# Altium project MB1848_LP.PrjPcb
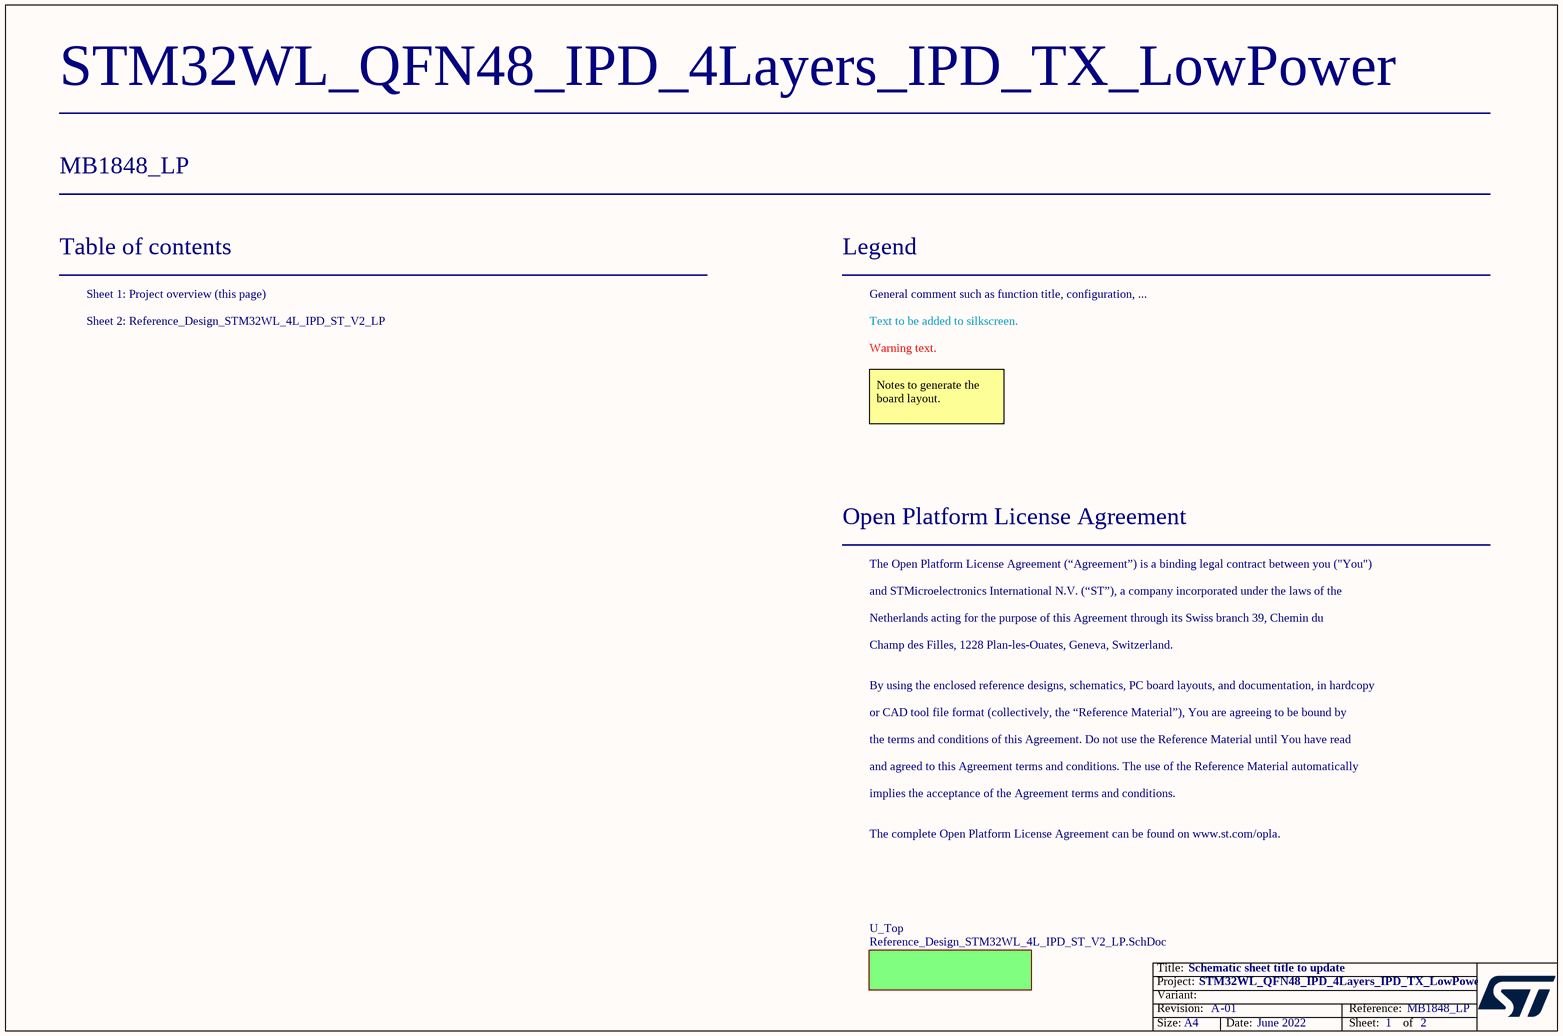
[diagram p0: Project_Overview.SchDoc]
Board_Assembly_Revision: 01; Board_Document_Date: June 2022; Board_Name: STM32WL_QFN48_IPD_4Layers_IPD_TX_LowPower; Board_PCB_Revision: A; Board_Reference: MB1848_LP
2 sheets, 71 parts. Net scope: flat (ports and power ports of the same name join across sheets).
Board file: MB1848_LP.PcbDoc
Sheets:
  Project_Overview.SchDoc
    U_Top = Reference_Design_STM32WL_4L_IPD_ST_V2_LP.SchDoc

## Sheet Project_Overview.SchDoc: Schematic sheet title to update
size A4; Date: Not used; ApprovedBy: Not used; CheckedBy: Not used; Author: Not used; CompanyName: STMicroelectronics; DrawnBy: Not used; Engineer: Not used; Organization: Not used; Address1: Not used; Address2: Not used; Address3: Not used; Address4: Not used; DocumentNumber: Not used; Revision: Not used; SheetNumber: 1; SheetTotal: 2

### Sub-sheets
U_Top = Reference_Design_STM32WL_4L_IPD_ST_V2_LP.SchDoc: no entries

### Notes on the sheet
- Table of contents
- Sheet 1: Project overview (this page)
- Legend
- General comment such as function title, configuration, ...
- Sheet 2: Reference_Design_STM32WL_4L_IPD_ST_V2_LP
- Text to be added to silkscreen.
- Warning text.
- Notes to generate the board layout.
- Open Platform License Agreement
- The Open Platform License Agreement (“Agreement”) is a binding legal contract between you ("You")
- and STMicroelectronics International N.V. (“ST”), a company incorporated under the laws of the
- Netherlands acting for the purpose of this Agreement through its Swiss branch 39, Chemin du
- Champ des Filles, 1228 Plan-les-Ouates, Geneva, Switzerland.
- By using the enclosed reference designs, schematics, PC board layouts, and documentation, in hardcopy
- or CAD tool file format (collectively, the “Reference Material”), You are agreeing to be bound by
- the terms and conditions of this Agreement. Do not use the Reference Material until You have read
- and agreed to this Agreement terms and conditions. The use of the Reference Material automatically
- implies the acceptance of the Agreement terms and conditions.
- The complete Open Platform License Agreement can be found on www.st.com/opla.

## Sheet Reference_Design_STM32WL_4L_IPD_ST_V2_LP.SchDoc: Schematic sheet title to update
size A3; Date: Not used; ApprovedBy: Not used; CheckedBy: Not used; Author: Not used; CompanyName: STMicroelectronics; DrawnBy: Not used; Engineer: Not used; Organization: Not used; Address1: Not used; Address2: Not used; Address3: Not used; Address4: Not used; DocumentNumber: Not used; Revision: Not used; SheetNumber: 2; SheetTotal: 2
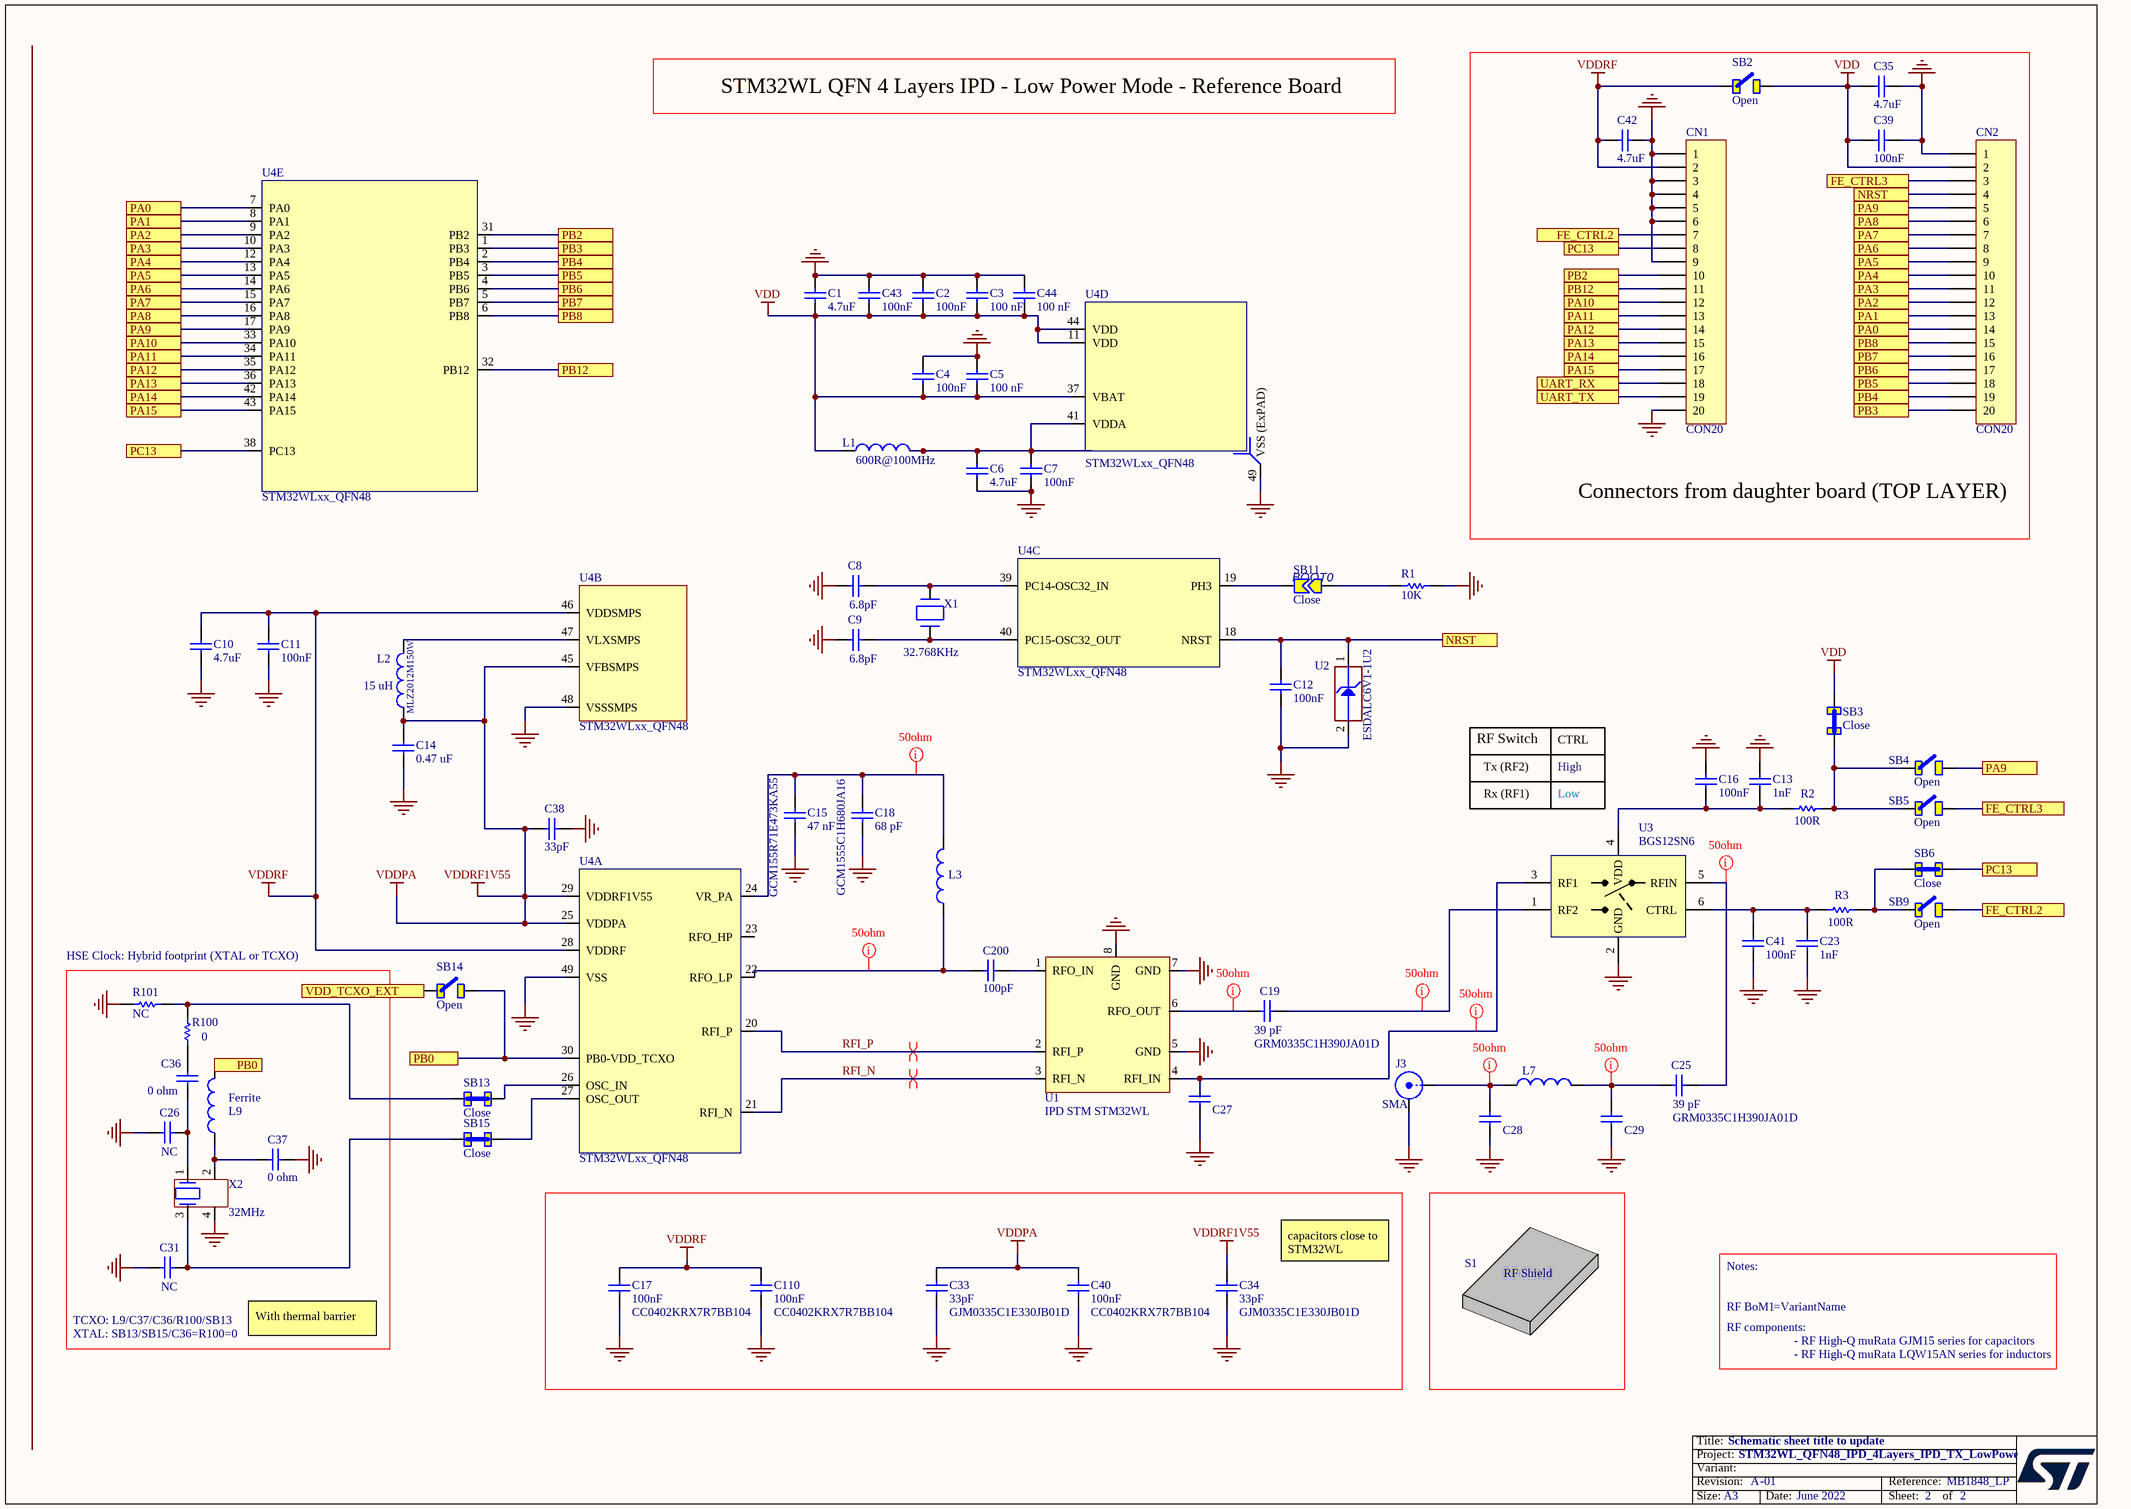
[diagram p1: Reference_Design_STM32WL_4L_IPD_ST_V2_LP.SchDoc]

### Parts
C1  value 4.7uF  [CAPC1608X09N]
C2  value 100nF  [CAPC1005X06N]
C3  value 100 nF  [0201]
C4  value 100nF  [CAPC1005X06N]
C5  value 100 nF  [0201]
C6  value 4.7uF  [CAPC1608X09N]
C7  value 100nF  [CAPC1005X06N]
C8  value 6.8pF  [0402]  (hidden comment: Capacitor)
C9  value 6.8pF  [0402]  (hidden comment: Capacitor)
C10  value 4.7uF  [CAPC1608X09N]
C11  value 100nF  [CAPC1005X06N]
C12  value 100nF  [0402]
C13  value 1nF  [0201]  (hidden comment: MCD-00198)
C14  value 0.47 uF  [CAPC1608X09N]
C15  value 47 nF  Manufacturer_Part_Number: GCM155R71E473KA55  [0402]
C16  value 100nF  [0201]  (hidden comment: MCD-00102)
C17  value 100nF  Manufacturer_Part_Number: CC0402KRX7R7BB104  [CAPC1005X06N]
C18  value 68 pF  Manufacturer_Part_Number: GCM1555C1H680JA16  [0402]
C19  value 39 pF  Manufacturer_Part_Number: GRM0335C1H390JA01D  [rlc_201_smd]  (hidden comment: RFCapacitor_201)
C23  value 1nF  [0201]  (hidden comment: MCD-00198)
C25  value 39 pF  Manufacturer_Part_Number: GRM0335C1H390JA01D  [rlc_201_smd]  (hidden comment: RFCapacitor_201)
C26  value NC  [0402]  (hidden comment: Capacitor)
C27  NC  [0201]  (value not drawn)
C28  RFCapacitor_201  [rlc_201_smd]  (value not drawn)
C29  RFCapacitor_201  [rlc_201_smd]  (value not drawn)
C31  value NC  [0402]  (hidden comment: Capacitor)
C33  value 33pF  Manufacturer_Part_Number: GJM0335C1E330JB01D  [0201]
C34  value 33pF  Manufacturer_Part_Number: GJM0335C1E330JB01D  [0201]
C35  value 4.7uF  [CAPC1608X09N]
C36  value 0 ohm  [0402]
C37  value 0 ohm  [0402]
C38  value 33pF  [0201]
C39  value 100nF  [CAPC1005X06N]
C40  value 100nF  Manufacturer_Part_Number: CC0402KRX7R7BB104  [CAPC1005X06N]
C41  value 100nF  [0201]  (hidden comment: MCD-00102)
C42  value 4.7uF  [CAPC1608X09N]
C43  value 100nF  [CAPC1005X06N]
C44  value 100 nF  [0201]
C110  value 100nF  Manufacturer_Part_Number: CC0402KRX7R7BB104  [CAPC1005X06N]
C200  value 100pF  [0201]  (hidden comment: MCD-00198)
CN1  CON20  [CO_SAMTEC_TSW-120-07-x-S]
CN2  CON20  [CO_SAMTEC_TSW-120-07-x-S]
J3  SMA  [SMA_AMPHENOL_50ohms_Edge_PCB]
L1  value 600R@100MHz  [INDC1608X95N]
L2  value 15 uH  Manufacturer_Part_Number: MLZ2012M150W  [INDC2012X13N]
L3  MCD-01330  [IND_MURATA_LQW15A]  (value not drawn)
L7  Ferrite  [rlc_201_smd]  (value not drawn)
L9  Ferrite  [IND_MURATA_LQW15A]
R1  value 10K  [RESC1608X05N]
R2  value 100R  [0201]  (hidden comment: MCD-00119)
R3  value 100R  [0201]  (hidden comment: MCD-00119)
R100  value 0  [R0402]  (hidden comment: Resistor)
R101  value NC  [R0402]  (hidden comment: Resistor)
RF_BoM1  RF-BOM  (value not drawn)  (mechanical)
S1  RF-Shield  (value not drawn)  (mechanical)
SB2  Open  [SB_0402]
SB3  Close  [0201]
SB4  Open  [0201]
SB5  Open  [0201]
SB6  Close  [0201]
SB9  Open  [0201]
SB11  Close  [GC_0402]
SB13  Close  [SB_0402]
SB14  Open  [SB_0402]
SB15  Close  [SB_0402]
U1  IPD STM STM32WL  [IPD STM]
U2  Manufacturer_Part_Number: ESDALC6V1-1U2  [DIOM0603X03N]
U3  BGS12SN6  [TSNP-6-2]
U4  STM32WLxx_QFN48  [STM32WLxx_QFN48]  (parts A,B,C,D,E of 5)
X1  value 32.768KHz  [OSC_NDK_NX2012SA]  (hidden comment: XTAL_2_PINS)
X2  value 32MHz  [OSC_NDK_NX2016SA]

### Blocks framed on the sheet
Connectors from daughter board (TOP LAYER): C35 C39 C42 CN1 CN2 SB2

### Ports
FE_CTRL2, FE_CTRL3, NRST, PA0, PA1, PA2, PA3, PA4, PA5, PA6, PA7, PA8, PA9, PA10, PA11, PA12, PA13, PA14, PA15, PB0, PB2, PB3, PB4, PB5, PB6, PB7, PB8, PB12, PC13, UART_RX, UART_TX, VDD_TCXO_EXT

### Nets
GND: C1.1 C2.1 C3.1 C4.1 C5.1 C6.2 C7.2 C8.2 C9.2 C10.2 C11.2 C12.2 C13.1 C14.2 C15.2 C16.1 C17.2 C18.1 C23.1 C26.2 C27.1 C28.1 C29.1 C31.2 C33.1 C34.1 C35.1 C37.1 C38.2 C39.2 C40.2 C41.2 C42.2 C43.1 C44.1 C110.2 CN1.1 CN1.3 CN1.4 CN1.5 CN1.6 CN1.9 CN1.20 CN2.1 J3.2(GND) R1.1 R101.2 U1.5(GND) U1.7(GND) U1.8(GND) U2.2(GND) U3.2(GND) U4.48(VSSSMPS) U4.49(VSS_(ExPAD)) X2.4
VDD: C1.2 C2.2 C3.2 C4.2 C5.2 C35.2 C39.1 C43.2 C44.2 CN2.2 L1.1 SB2.1 SB3.1 U4.11(VDD) U4.37(VBAT) U4.44(VDD)
VDDPA: C14.1 C33.2 C34.2 C38.1 C40.1 L2.1 U4.25(VDDPA) U4.29(VDDRF1V55) U4.45(VFBSMPS)  [also labelled VDDRF1V55]
VDDRF: C10.1 C11.1 C17.1 C42.1 C110.1 CN1.2 SB2.2 U4.28(VDDRF) U4.46(VDDSMPS)
RFI_N: U1.3(RFI_N) U4.21(RFI_N)
RFI_P: U1.2(RFI_P) U4.20(RFI_P)
NetC6_1: C6.1 C7.1 L1.2 U4.41(VDDA)
NetC8_1: C8.1 U4.39(PC14-OSC32_IN) X1.2(X2)
NetC9_1: C9.1 U4.40(PC15-OSC32_OUT) X1.1(X1)
NetC12_1: C12.1 CN2.4 U2.1(IO1) U4.18(NRST) ; port NRST
NetC13_2: C13.2 C16.2 R2.1 U3.4(VDD)
NetC15_1: C15.1 C18.2 L3.1 U4.24(VR_PA)
NetC19_1: C19.1 U3.1(RF2)
NetC19_2: C19.2 U1.6(RFO_OUT)
NetC23_2: C23.2 C41.1 R3.1 U3.6(CTRL)
NetC25_1: C25.1 U3.5(RFIN)
NetC25_2: C25.2 C29.2 L7.1
NetC26_1: C26.1 C36.2 X2.1
NetC27_2: C27.2 U1.4(RFI_IN) U3.3(RF1)
NetC28_2: C28.2 J3.1(Signal) L7.2
NetC31_1: C31.1 SB15.2 X2.3
NetC36_1: C36.1 R100.2
NetC37_2: C37.2 L9.1 X2.2
NetC200_1: C200.1 U1.1(RFO_IN)
NetC200_2: C200.2 L3.2 U4.22(RFO_LP)
NetCN1_7: CN1.7 SB9.1 ; port FE_CTRL2
NetCN1_8: CN1.8 SB6.1 U4.38(PC13) ; port PC13
NetCN1_10: CN1.10 U4.31(PB2) ; port PB2
NetCN1_11: CN1.11 U4.32(PB12) ; port PB12
NetCN1_12: CN1.12 U4.33(PA10) ; port PA10
NetCN1_13: CN1.13 U4.34(PA11) ; port PA11
NetCN1_14: CN1.14 U4.35(PA12) ; port PA12
NetCN1_15: CN1.15 U4.36(PA13) ; port PA13
NetCN1_16: CN1.16 U4.42(PA14) ; port PA14
NetCN1_17: CN1.17 U4.43(PA15) ; port PA15
NetCN1_18: CN1.18 ; port UART_RX
NetCN1_19: CN1.19 ; port UART_TX
NetCN2_3: CN2.3 SB5.1 ; port FE_CTRL3
NetCN2_5: CN2.5 SB4.1 U4.17(PA9) ; port PA9
NetCN2_6: CN2.6 U4.16(PA8) ; port PA8
NetCN2_7: CN2.7 U4.15(PA7) ; port PA7
NetCN2_8: CN2.8 U4.14(PA6) ; port PA6
NetCN2_9: CN2.9 U4.13(PA5) ; port PA5
NetCN2_10: CN2.10 U4.12(PA4) ; port PA4
NetCN2_11: CN2.11 U4.10(PA3) ; port PA3
NetCN2_12: CN2.12 U4.9(PA2) ; port PA2
NetCN2_13: CN2.13 U4.8(PA1) ; port PA1
NetCN2_14: CN2.14 U4.7(PA0) ; port PA0
NetCN2_15: CN2.15 U4.6(PB8) ; port PB8
NetCN2_16: CN2.16 U4.5(PB7) ; port PB7
NetCN2_17: CN2.17 U4.4(PB6) ; port PB6
NetCN2_18: CN2.18 U4.3(PB5) ; port PB5
NetCN2_19: CN2.19 U4.2(PB4) ; port PB4
NetCN2_20: CN2.20 U4.1(PB3) ; port PB3
NetL2_2: L2.2 U4.47(VLXSMPS)
NetL9_2: L9.2 SB14.1 U4.30(PB0-VDD_TCXO) ; port PB0
NetR1_2: R1.2 SB11.1
NetR2_2: R2.2 SB3.2 SB4.2 SB5.2
NetR3_2: R3.2 SB6.2 SB9.2
NetR100_1: R100.1 R101.1 SB13.2
NetSB11_2: SB11.2 U4.19(PH3)
NetSB13_1: SB13.1 U4.26(OSC_IN)
NetSB14_2: SB14.2 ; port VDD_TCXO_EXT
NetSB15_1: SB15.1 U4.27(OSC_OUT)

Not connected (* = marked no-connect by the designer): U4 23(RFO_HP)

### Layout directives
net class 50ohm: NetC15_1, NetC19_1, NetC19_2, NetC25_1, NetC25_2, NetC27_2, NetC28_2, NetC200_2
differential pair: RFI_N, RFI_P

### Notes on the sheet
- STM32WL QFN 4 Layers IPD - Low Power Mode - Reference Board
- (near SB11) BOOT0
- RF Switch
- Tx (RF2)
- CTRL
- High
- Rx (RF1)
- Low
- HSE Clock: Hybrid footprint (XTAL or TCXO)
- capacitors close to STM32WL
- (near C31) TCXO: L9/C37/C36/R100/SB13
- Notes:
- XTAL: SB13/SB15/C36=R100=0
- With thermal barrier
- RF components:
- (near RF_BoM1) - RF High-Q muRata GJM15 series for capacitors
- (near RF_BoM1) - RF High-Q muRata LQW15AN series for inductors

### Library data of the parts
C1 C6 C10 C35 C42 = MCD-00009: Capacitor, MLCC, 4.7uF, 16V, X5R, 10%, 0603, T=0.8mm; Manufacturer_Part_Number: CC0603KRX5R7BB475; Manufacturer: YAGEO
C2 C4 C7 C11 C12 C39 C43 = MCD-00102: Capacitor, MLCC, 100nF, 16V, X7R, 10%, 0402, T=0,5mm; Manufacturer_Part_Number: CC0402KRX7R7BB104; Manufacturer: YAGEO
C3 C5 C44 = MCD-00102: Multilayer Ceramic Capacitors MLCC - SMD/SMT 0201 25VDC 0.1uF 10% X5R 0.3mm; Manufacturer_Part_Number: C0603X5R1E104K030BB; Manufacturer: TDK
C8 C9 = MCD-00003: Capacitor, MLCC, 6.8pF, 50V, NPO, +-0.1pF, 0402, T=0.5mm; Manufacturer_Part_Number: GRM1555C1H6R8BA01; Manufacturer: MURATA
C13 C23 = MCD-00198: Multilayer ceramic capacitors X7R ±10%, 50V; Manufacturer_Part_Number: GRM033R71H102KA12D; Manufacturer: MURATA
C14 = MCD-00009: Capacitor, MLCC, 4.7 uF, 16V, X5R, 10%, 0603, T=0.8mm; Manufacturer_Part_Number: CC0603KRX5R7BB474; Manufacturer: YAGEO
C15 = MCD-01123: Capacitor, MLCC,47nF, 16V, X7R, 10%, 0402, T=0.5mm; Manufacturer: MURATA
C16 C41 = MCD-00102: Multilayer ceramic capacitors X5R ±10%, 10V; Manufacturer_Part_Number: GRM033R61A104KE15D; Manufacturer: MURATA
C17 C40 C110 = MCD-00102: Capacitor, MLCC, 100nF, 16V, X7R, 10%, 0402, T=0,5mm; Manufacturer: YAGEO
C18 = MCD-01123: Capacitor, MLCC,68pF, 50V, C0G, 1%, 0402, T=0.5mm; Manufacturer: MURATA
C19 C25 = RFCapacitor_201: Multilayer ceramic capacitors COG ±5%, 50V; Manufacturer: MURATA
C26 C31 = MCD-00003: Not connected
C27 = RFCapacitor_201: RF Capacitor High-Q, 0201
C28 C29 = RFCapacitor_201: RF Capacitor High-Q, 0201; Value: NC
C33 C34 = MCD-00277: Multilayer Ceramic Capacitors MLCC - SMD/SMT 0201 33pF 25volts C0G 5%; Manufacturer: MURATA
C36 C37 = MCD-00277: Capacitor, MLCC, 33pF, 50V, NPO, 2%, 0402, T=0,5mm; Manufacturer_Part_Number: RCS04020000Z0ED; Manufacturer: Vishay / Dale
C38 = MCD-01123: Multilayer Ceramic Capacitors MLCC - SMD/SMT 0201 33pF 25volts C0G 5%; Manufacturer_Part_Number: GJM0335C1E330JB01D; Manufacturer: MURATA
C200 = MCD-00198: Multilayer ceramic capacitors COG +/-5%, 50V; Manufacturer_Part_Number: GRM033R71H102KA12D; Manufacturer: MURATA
CN1 CN2 = CON20: Connector right-angle, pitch 2.54mm, 20 contacts; Manufacturer: SAMTEC; Manufacturer_Part_Number: TSW-120-07-L-S
J3 = SMA: SMA Straight Connector; Manufacturer: Johnson / Cinch Connectivity Solutions; Manufacturer_Part_Number: 142-0701-841
L1 = MCD-00047: SMD Chip ferrite bead, 600R@100MHz +/-25%, 350mA, 500mohm DC, 0603, T=0.8mm; Manufacturer_Part_Number: BK1608HS601-T; Manufacturer: Taiyo Yuden
L2 = MCD-01433: MLZ2012 Multilayer Shielded Inductor 15 uH, ±5%; Manufacturer: TDK
L3 = MCD-01330: Inductor, 47nH, +-0.1nH, 140mA, 0402; Value: NC
L7 = RFInductor_201: Thick Film Resistor ±5%, 1/20W; Manufacturer_Part_Number: CRCW02010000Z0ED; Manufacturer: Vishay/Dale; Value: 0R
L9 = MCD-01330: Not connected; Part_Type: Ferrite bead; Value: NC; Provided_By: SUBCO; Initial_Board_Reference: MB1402
R1 = MCD-00220: Resistor,10K,0603,1%,1/10W; Manufacturer_Part_Number: RC0603FR-0710KL; Manufacturer: YAGEO
R2 R3 = MCD-00119: Thick Film Resistors - SMD 1/20watt 100ohms 5% 200ppm; Manufacturer_Part_Number: CRCW0201100RJNED; Manufacturer: Vishay / Dale
R100 = MCD-00052: Resistor,0R,0402,5%,1/16W; Manufacturer_Part_Number: RC0402JR-070RL; Manufacturer: YAGEO; Provided_By: SUBCO; Initial_Board_Reference: MB1274
R101 = MCD-00052: Not connected; Manufacturer: YAGEO; Provided_By: SUBCO; Initial_Board_Reference: MB1274
S1 = RF-Shield: RF Shield Frame + Cover without apertures; Manufacturer: Masach Tech; Manufacturer_Part_Number: MS409-10
SB2 SB4 SB5 SB9 SB14 = SB_Open: Solder Bridge Open [0402] (Unpopulated)
SB3 SB6 = SB_0Ohm: Thick Film Resistors - SMD 1/20watt ZEROohm Jumper; Manufacturer: Vishay / Dale; Manufacturer_Part_Number: CRCW02010000Z0ED; VALUE: 0
SB11 = Strap2: Solder Jumper - Close; Manufacturer: Vishay / Dale; Manufacturer_Part_Number: RCS04020000Z0ED
SB13 SB15 = SB_0Ohm: Solder Bridge 0R [0402] (Populated with 0 Ohm); Manufacturer: Vishay / Dale; Manufacturer_Part_Number: RCS04020000Z0ED; VALUE: 0
U1 = IPD ST STM32WL: Manufacturer: STMICROELECTRONICS
U2 = MCD-00170: ESD protection 6V1; Manufacturer: STMICROELECTRONICS
U3 = BGS12SN6: DC switch - Ultra-Low  SPDT analog switch; Manufacturer: INFINEON
U4 = STM32WLxx_QFN48: STM32WL ARM MCU Multiprotocol LPWAN 32-bit Arm Cortex-M4 MCUs LoRa (G)FSK-MSK BPSK; Manufacturer_Part_Number: STM32WLE5CC; Manufacturer: STMicroelectronics
X1 = MCD-01479: Crystal 32.768kHz, 6pF, -+20PPM, R=80K, SMD; Manufacturer_Part_Number: NX2012SA 32.768KHz EXS00A-MU00527; Manufacturer: NDK
X2 = MCD-01446: Crystal 32 MHz, 8pF, -+10 PPM, R=60Ω, SMD; Manufacturer_Part_Number: NX2016SA 32MHz EXS00A-CS06465; Manufacturer: NDK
